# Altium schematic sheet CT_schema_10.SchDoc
size 277 x 170 mm
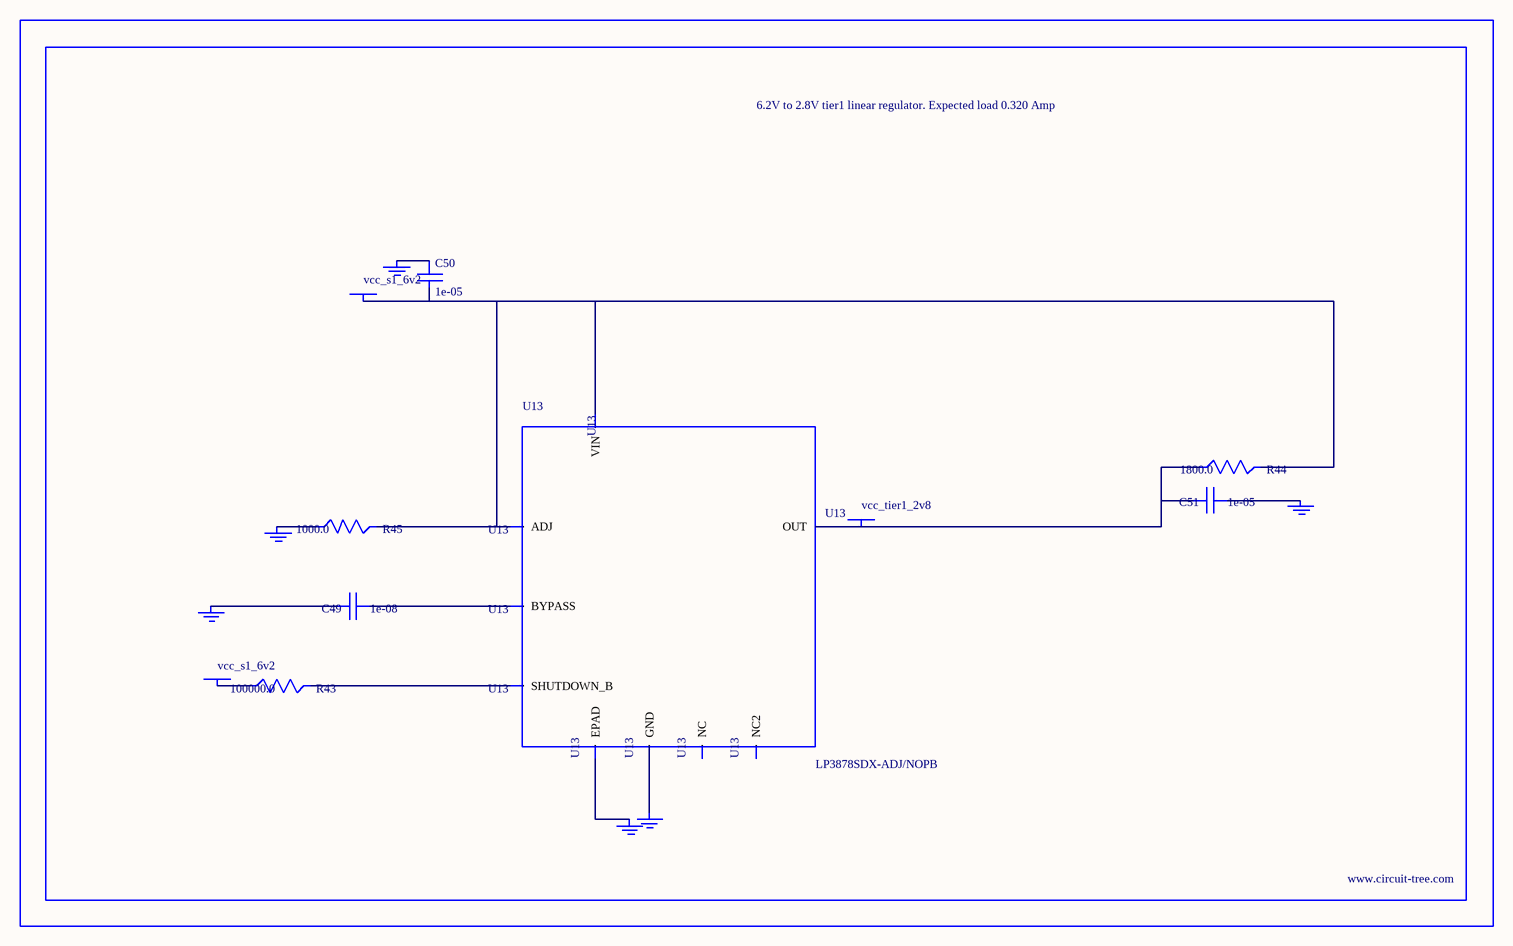
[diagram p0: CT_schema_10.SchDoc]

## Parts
BORDER9  (no value)
C49  1e-08  [C0402]
C50  1e-05  [C1206]
C51  1e-05  [C1210]
GND_INSTANCE_9_0  (no value)
GND_INSTANCE_9_1  (no value)
GND_INSTANCE_9_2  (no value)
GND_INSTANCE_9_3  (no value)
GND_INSTANCE_9_4  (no value)
GND_INSTANCE_9_5  (no value)
POWER_INSTANCE_9_0  vcc_s1_6v2
POWER_INSTANCE_9_1  vcc_s1_6v2
POWER_INSTANCE_9_2  vcc_tier1_2v8
R43  100000.0  [R0603]
R44  1800.0  [R0603]
R45  1000.0  [R0603]
U13  LP3878SDX-ADJ/NOPB  [WSON-8]

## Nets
NetC49_1: C49.1 U13.1(BYPASS)
NetC49_2: C49.2 GND_INSTANCE_9_0.0(GND)
NetC50_1: C50.1 GND_INSTANCE_9_1.0(GND)
NetC50_2: C50.2 POWER_INSTANCE_9_0.0(PWR) R44.2 R45.2 U13.4(VIN) U13.6(ADJ)
NetC51_1: C51.1 GND_INSTANCE_9_2.0(GND)
NetC51_2: C51.2 POWER_INSTANCE_9_2.0(PWR) R44.1 U13.5(OUT)
NetGND_INSTANCE_9_3_0: GND_INSTANCE_9_3.0(GND) R45.1
NetGND_INSTANCE_9_4_0: GND_INSTANCE_9_4.0(GND) U13.PAD(EPAD)
NetGND_INSTANCE_9_5_0: GND_INSTANCE_9_5.0(GND) U13.3(GND)
NetPOWER_INSTANCE_9_1_0: POWER_INSTANCE_9_1.0(PWR) R43.1
NetR43_2: R43.2 U13.8(SHUTDOWN_B)

Not connected (* = marked no-connect by the designer): U13 2(NC) 7(NC2)

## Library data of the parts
BORDER9 = BORDER_PAGE9
C49 = C0402C103K3RAC
C50 = C1206C106K3RACTU
C51 = GRM32DR61E106MA12L
GND_INSTANCE_9_0-GND_INSTANCE_9_5 = GND
POWER_INSTANCE_9_0-POWER_INSTANCE_9_2 = PWR
R43 = RC0603JR-07100KL
R44 = RC0603JR-071K8L
R45 = RC0603JR-071KL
